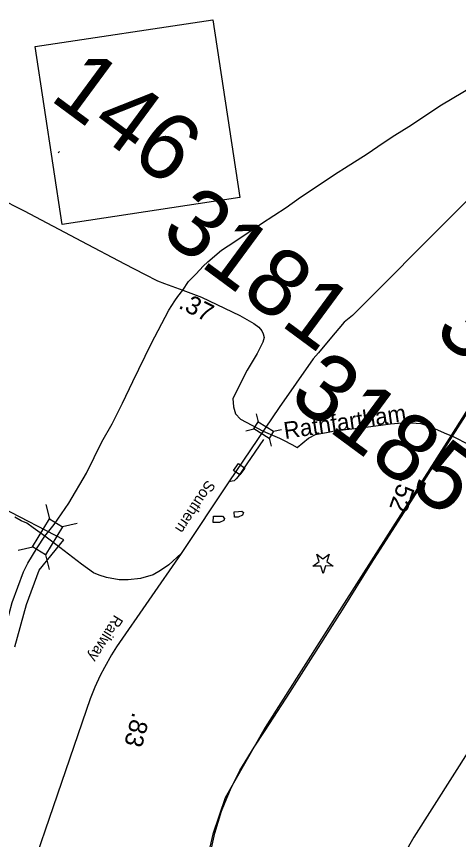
# Model space of a CAD drawing. Extents: x 945666 to 965748, y 644452 to 663300.
# Drawn here: x 953350 to 953745, y 658594 to 659330 of the extents above; entities that cross this region are included whole.
import ezdxf

# ---------------------------------------------------------------- set-up
doc = ezdxf.new("R2010")
doc.units = 0
for name, color, linetype in [('Exist Boundary Political City Limit New', 7, 'Continuous'), ('Exist Civil Patrol Station CELL', 7, 'Continuous'), ('Exist Hydrographic Misc Water Feature', 7, 'Continuous'), ('Exist Hydrographic Pond Under 1500 Sq Ft', 7, 'Continuous'), ('Exist Railroad Mainline', 7, 'Continuous'), ('Exist Railroad Mainline Label', 7, 'Continuous'), ('Exist Railroad Siding', 7, 'Continuous'), ('Exist Railroad Station CELL', 7, 'Continuous'), ('Exist Railroad Structure Bridge CELL', 7, 'Continuous'), ('Exist Road Primary NC Attributed', 7, 'Continuous'), ('Exist Road Primary NC Shield CELL', 7, 'Continuous'), ('Exist Road Primary NC Shield Number Label', 7, 'Continuous'), ('Exist Road Primary US Mileage Hundredths English Label', 7, 'Continuous'), ('Exist Road Primary US UnDivided 4 Lane Attributed', 7, 'Continuous'), ('Exist Road Secondary Mileage Tenths English Label', 7, 'Continuous'), ('Exist Road Secondary Structure Standard Bridge CELL', 7, 'Continuous'), ('Exist Road Secondary Type 51 Attributed', 7, 'Continuous'), ('Exist Road Secondary Type 51 Label', 7, 'Continuous'), ('Old_Level_1', 7, 'Continuous'), ('Old_Level_28', 7, 'Continuous'), ('Old_Level_49', 7, 'Continuous')]:
    doc.layers.add(name, color=color, linetype=linetype)

msp = doc.modelspace()

# ---------------------------------------------------------------- linework, layer by layer
at = {"layer": 'Exist Boundary Political City Limit New'}
for points in [[(953767.75, 659001.98), (953738.57, 658955.88), (953640.65, 658801.94), (953571.94, 658694.17), (953536.21, 658631.49), (953525.19, 658598.82), (953510.51, 658535.42)], [(953347.95, 658766.22), (953358.52, 658804.17), (953369.74, 658834.69), (953391.97, 658862.05), (953336.71, 658890.38)]]:
    msp.add_lwpolyline(points, dxfattribs=at)
at = {"layer": 'Exist Civil Patrol Station CELL'}
msp.add_lwpolyline([(953618.15, 658849.17), (953623.69, 658845.08), (953629.33, 658849.21), (953627.18, 658842.5), (953632.68, 658838.45), (953625.91, 658838.56), (953623.8, 658831.98), (953621.64, 658838.54), (953614.73, 658838.52), (953620.31, 658842.6)], close=True, dxfattribs=at)
at = {"layer": 'Exist Hydrographic Misc Water Feature'}
msp.add_line((953388.05, 659209.1), (953386.88, 659207.82), dxfattribs=at)
at = {"layer": 'Exist Hydrographic Pond Under 1500 Sq Ft'}
for points in [[(953525.86, 658883.02), (953528.72, 658883.17), (953533.95, 658883.04), (953535.7, 658881.04), (953535.1, 658879.14), (953531.02, 658877.33), (953525.49, 658877.49), (953525.86, 658883.02)], [(953544.26, 658886.94), (953548.12, 658887.19), (953551.08, 658887.49), (953552.74, 658886.21), (953551.83, 658883.92), (953547.75, 658882.1), (953544.68, 658882.1), (953544.26, 658886.94)]]:
    msp.add_lwpolyline(points, dxfattribs=at)
at = {"layer": 'Exist Railroad Mainline'}
msp.add_line((953539.4, 658913.9), (953496.77, 658849.77), dxfattribs=at)
for points in [[(953832.76, 659245.77), (953650.24, 659062.44), (953642.73, 659056.39), (953629.76, 659041.2), (953619.62, 659028.99), (953614.95, 659023.55), (953584.63, 658980.2), (953539.4, 658913.9)], [(953570.51, 658951.7), (953547.88, 658918.56), (953546.15, 658916.45), (953544.12, 658914.79), (953542.47, 658914.33), (953539.4, 658913.9)], [(953496.77, 658849.77), (953439.11, 658766.27), (953434.45, 658759.1), (953428.22, 658747.98), (953424.48, 658740.75), (953419.55, 658730.34), (953416.53, 658722.78), (953415.54, 658719.88), (953330.81, 658473.62), (953263.93, 658277.51), (953252.36, 658242.54), (953250.06, 658235.49), (953248.62, 658228.64), (953246.69, 658221.95), (953244.11, 658211.67), (953241.48, 658199.5)]]:
    msp.add_lwpolyline(points, dxfattribs=at)
at = {"layer": 'Exist Railroad Siding'}
msp.add_lwpolyline([(953496.77, 658849.77), (953485.79, 658839.64), (953478.4, 658834.39), (953471.81, 658830.77), (953460.56, 658827.32), (953449.44, 658826.17), (953441.49, 658826.12), (953430.21, 658828.12), (953423.52, 658830.42), (953418.54, 658832.57), (953407.73, 658840.07), (953388.26, 658855.07), (953374.86, 658865.19), (953364.57, 658872.69), (953358.9, 658876.71), (953353.63, 658879), (953347.97, 658882.06)], dxfattribs=at)
at = {"layer": 'Exist Railroad Station CELL'}
msp.add_lwpolyline([(953553.74, 658926.06), (953549.33, 658919.9), (953543.71, 658923.92), (953548.12, 658930.08)], close=True, dxfattribs=at)
at = {"layer": 'Exist Railroad Structure Bridge CELL'}
for p, q in [((953375.84, 658893.58), (953379.01, 658880.6)), ((953403.69, 658876.67), (953390.7, 658873.5)), ((953364.03, 658855.45), (953351.05, 658852.27)), ((953375.46, 658848.51), (953378.63, 658835.53))]:
    msp.add_line(p, q, dxfattribs=at)
msp.add_lwpolyline([(953390.7, 658873.5), (953375.51, 658848.48), (953363.82, 658855.57), (953379.01, 658880.6)], close=True, dxfattribs=at)
at = {"layer": 'Exist Road Primary NC Attributed'}
msp.add_lwpolyline([(953053.63, 659332.58), (953071.49, 659316.01), (953083.1, 659305.53), (953101.11, 659290.38), (953111.77, 659282.31), (953135.33, 659266.77), (953155.37, 659255.42), (953202.07, 659232.09), (953236.02, 659215.21), (953253.2, 659206.53), (953269.3, 659198.82), (953308.95, 659179.81), (953356.31, 659156.07), (953407.63, 659128.93), (953446.02, 659108.53), (953464.07, 659099.3), (953475.58, 659093.45), (953481.88, 659090.88), (953498.47, 659085.2)], dxfattribs=at)
at = {"layer": 'Exist Road Primary NC Shield CELL'}
msp.add_lwpolyline([(953366.26, 659302.75), (953525.27, 659326.77), (953549.29, 659167.77), (953390.28, 659143.74)], close=True, dxfattribs=at)
at = {"layer": 'Exist Road Primary US UnDivided 4 Lane Attributed'}
for points in [[(953498.47, 659085.2), (953503.5, 659092.82), (953510.2, 659099.57), (953516.57, 659106.62), (953520.84, 659110.36), (953532.79, 659120.84), (953544.92, 659128.66), (953568.71, 659144.51), (953590.76, 659158.99), (953603.62, 659168.04), (953614, 659174.93), (953634.15, 659188.36), (953646.18, 659196.1), (953654.22, 659201.29), (953663.32, 659206.84), (953677.42, 659216.6), (953687.91, 659223.59), (953700.38, 659231.31), (953729.79, 659250.65), (953766.36, 659272.53)], [(953739.6, 658954.55), (953781.83, 659020.84), (953824.56, 659087.83), (953833.32, 659102.74), (953872.78, 659163.87)], [(953374.86, 658865.19), (953383.14, 658875.76), (953396.51, 658894.7), (953412.17, 658921.49), (953425.8, 658949.54), (953434.99, 658965.68), (953444.36, 658984.19), (953453.48, 659003.37), (953470.04, 659036.96), (953485.94, 659067.08), (953491.05, 659075.43), (953493.79, 659079.53), (953498.47, 659085.2)], [(953667.23, 658841.11), (953696.68, 658887.06), (953739.6, 658954.55)], [(953257.84, 658557.66), (953260.82, 658574.81), (953264.56, 658586.6), (953267.02, 658594.06), (953296.49, 658660.23), (953306.25, 658683.27), (953312.16, 658695.11), (953317.78, 658708.11), (953323.45, 658724.35), (953327.83, 658739.61), (953334.9, 658765.48), (953345.72, 658806.06), (953355.87, 658833.24), (953359.65, 658840.96), (953367.9, 658854.73), (953374.86, 658865.19)], [(953571.84, 658691.56), (953594.1, 658725.57), (953636.29, 658792.06), (953641.28, 658799.47), (953667.23, 658841.11)], [(953506, 658505.53), (953527.07, 658599.84), (953532.9, 658619.39), (953536.27, 658627.4), (953540.91, 658638.87), (953549.23, 658655.92), (953562.23, 658676.57), (953571.84, 658691.56)]]:
    msp.add_lwpolyline(points, dxfattribs=at)
at = {"layer": 'Exist Road Secondary Structure Standard Bridge CELL'}
for p, q in [((953564.01, 658974.59), (953565.7, 658967.43)), ((953554.6, 658959.35), (953561.75, 658961.04)), ((953579.38, 658958.94), (953586.54, 658960.63)), ((953575.52, 658952.69), (953577.21, 658945.53))]:
    msp.add_line(p, q, dxfattribs=at)
msp.add_lwpolyline([(953565.7, 658967.43), (953579.4, 658958.97), (953575.45, 658952.57), (953561.75, 658961.04)], close=True, dxfattribs=at)
at = {"layer": 'Exist Road Secondary Type 51 Attributed'}
for points in [[(953498.47, 659085.2), (953514.89, 659078.68), (953549.45, 659062.31), (953561.91, 659055.36), (953566.27, 659052.06), (953569.04, 659048.66), (953570.22, 659046.03), (953570.95, 659042.69), (953569.89, 659038.44), (953564.79, 659028.37), (953555.87, 659013.49), (953543.1, 658988.22), (953543.53, 658980.84), (953545.5, 658974.48), (953549.96, 658969.63), (953570.16, 658959.05)], [(953600.69, 658944.37), (953610.8, 658952.7), (953616.97, 658955.94), (953628.43, 658958.06), (953635.58, 658959.74), (953655.18, 658961.81), (953675.43, 658964.46)], [(953675.43, 658964.46), (953684.04, 658965.58), (953698.4, 658966.73), (953711.14, 658965.86), (953718.6, 658963.48), (953734.12, 658956.74), (953739.6, 658954.55)], [(953739.6, 658954.55), (953754.75, 658946.78), (953760.99, 658945.21), (953768.88, 658944.91), (953775.52, 658947.51), (953780.23, 658950.63), (953789.58, 658955.33), (953797.78, 658958.82), (953804.57, 658962.11), (953807.13, 658963.16), (953809.51, 658963.37), (953812.75, 658962.68), (953815.95, 658960.49), (953820.18, 658951.84), (953822.03, 658948.79), (953823.69, 658946.32)], [(953570.16, 658959.05), (953584.92, 658952.74), (953588.44, 658951.02), (953595.98, 658947.05), (953600.69, 658944.37)]]:
    msp.add_lwpolyline(points, dxfattribs=at)
at = {"layer": 'Old_Level_28'}
msp.add_lwpolyline([(953773.55, 658703.93), (953704.85, 658596.15), (953669.11, 658533.48)], dxfattribs=at)

# ---------------------------------------------------------------- texts
at = {"layer": 'Exist Railroad Mainline Label'}
for s, rotation, p in [('Southern', 236.5961, (953520.03, 658916.05)), ('Railway', 238.23733, (953437.26, 658795.54))]:
    msp.add_text(s, height=9.743, rotation=rotation, dxfattribs=at).set_placement(p)
at = {"layer": 'Exist Road Primary NC Shield Number Label'}
msp.add_text('146', height=59.759, rotation=323.59084, dxfattribs=at).set_placement((953378.07, 659255.98))
at = {"layer": 'Exist Road Primary US Mileage Hundredths English Label'}
msp.add_text('.83', height=16.238, rotation=255.06721, dxfattribs=at).set_placement((953453.54, 658708.53))
at = {"layer": 'Exist Road Secondary Mileage Tenths English Label'}
msp.add_text('.52', height=16.238, rotation=250.68099, dxfattribs=at).set_placement((953692.77, 658918.92))
at = {"layer": 'Exist Road Secondary Type 51 Label'}
msp.add_text('Rathfartham', height=15, rotation=8.43249, dxfattribs=at).set_placement((953589.72, 658952.02))
at = {"layer": 'Old_Level_1'}
for s, p in [('3181', (953476.7, 659134.06)), ('3185', (953721.39, 659044.71)), ('3185', (953591.29, 658986.71))]:
    msp.add_text(s, height=60, rotation=323.59084, dxfattribs=at).set_placement(p)
at = {"layer": 'Old_Level_49'}
msp.add_text('.37', height=16.238, rotation=333.32286, dxfattribs=at).set_placement((953493.6, 659069.5))

doc.saveas('drawing.dxf')
